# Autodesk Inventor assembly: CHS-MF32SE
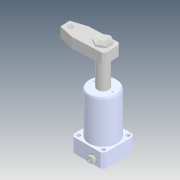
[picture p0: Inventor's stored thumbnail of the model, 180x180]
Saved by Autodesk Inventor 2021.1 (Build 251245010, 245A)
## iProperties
Created: 2020-02
Part Number: CHS-MF32SE
Description: STEP AP214
Document SubType Name: Assembly
Designer: user
Title: chs-mf32s-e_asm.STEP
Revision Number: ÈÎºÎ
Sending System: SolidWorks 2016
Preprocessor: SwSTEP 2.0
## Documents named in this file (9)
- D:\Vault_2016\Projekty\Clamptek\Hydraulic\CHS\CHS-32\Inventor\CHS-MF32SE\CHS-MF32SE.iam
- D:\Vault_2016\Projekty\Clamptek\Hydraulic\CHS\CHS-32\Inventor\CHS-MF32SE\CHS-32S-02-E_1_1.ipt
- D:\Vault_2016\Projekty\Clamptek\Hydraulic\CHS\CHS-32\Inventor\CHS-MF32SE\CHS-32S-01_7.ipt
- D:\Vault_2016\Projekty\Clamptek\Hydraulic\CHS\CHS-32\Inventor\CHS-MF32SE\M16_7.ipt
- D:\Vault_2016\Projekty\Clamptek\Hydraulic\CHS\CHS-32\Inventor\CHS-MF32SE\CHS-TXF-01_3.ipt
- D:\Vault_2016\Projekty\Clamptek\Hydraulic\CHS\CHS-32\Inventor\CHS-MF32SE\CHS-MF32-TXF-02_3.ipt
- D:\Vault_2016\Projekty\Clamptek\Hydraulic\CHS\CHS-32\Inventor\CHS-MF32SE\CHS-MF32-TXF-03_3.ipt
- D:\Vault_2016\Projekty\Clamptek\Hydraulic\CHS\CHS-32\Inventor\CHS-MF32SE\M6_3.ipt
- D:\Vault_2016\Projekty\Clamptek\Hydraulic\CHS\CHS-32\Inventor\CHS-MF32SE\CHS-MF32-E-BT.ipt
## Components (8 placed, 8 different names)
1. CHS-32S-02-E_1_1_1
2. CHS-32S-01_7_2
3. M16_7_3
4. CHS-TXF-01_3_4
5. CHS-MF32-TXF-02_3_5
6. CHS-MF32-TXF-03_3_6
7. M6_3_7
8. CHS-MF32-E-BT_8
